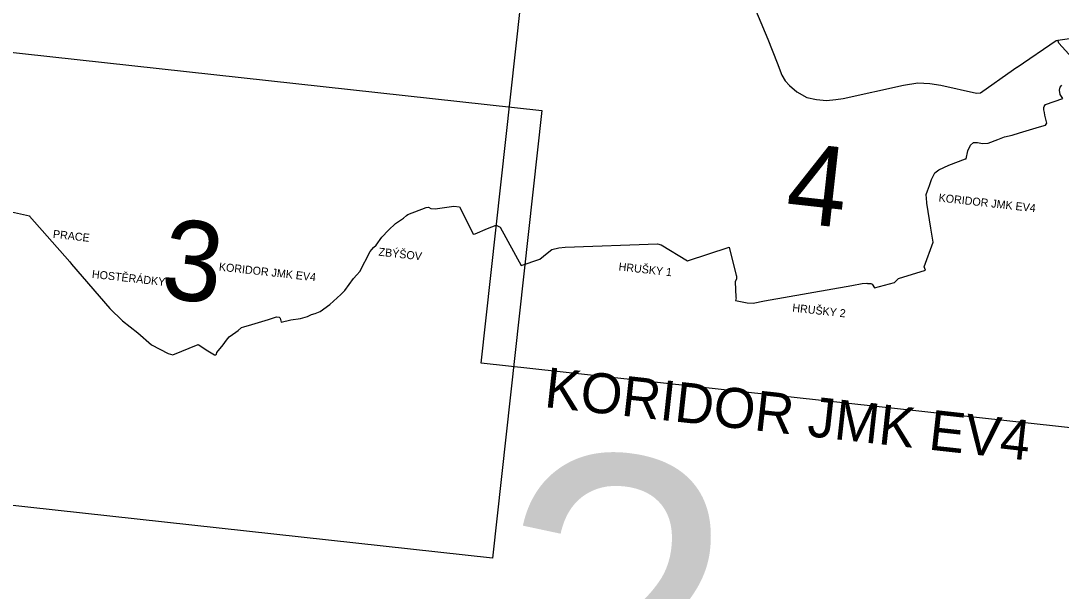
# Model space of a CAD drawing. Extents: x -678204 to -526855, y -1228851 to -1110393.
# Drawn here: x -587930 to -580130, y -1172295 to -1168017 of the extents above; entities that cross this region are included whole.
import ezdxf

# ---------------------------------------------------------------- set-up
doc = ezdxf.new("R2010")
doc.units = 0
for name, color, linetype in [('00_n_cyklo popisy', 7, 'Continuous'), ('00_n_cyklo popisy detaily', 7, 'Continuous'), ('00_n_cyklo provereni rekreacni hlavni', 7, 'Continuous'), ('00_n_cyklo provereni vedlejsi', 7, 'Continuous'), ('00_n_cyklo prujezdne podminecne rekreacni hlavni', 7, 'Continuous'), ('00_n_cyklo prujezdne rekreacni hlavni', 7, 'Continuous'), ('00_n_cyklo prujezdne rekreacni vedlejsi', 7, 'Continuous'), ('00_n_cyklo trasovani rekreacni hlavni', 7, 'Continuous'), ('00_n_cyklo trasovani rekreacni vedlejsi', 7, 'Continuous'), ('_HELP', 7, 'Continuous'), ('_HELP BIG', 7, 'Continuous')]:
    doc.layers.add(name, color=color, linetype=linetype)

msp = doc.modelspace()

# ---------------------------------------------------------------- linework, layer by layer
at = {"layer": '00_n_cyklo provereni rekreacni hlavni'}
for points in [[(-588022.2, -1169444.5), (-587865, -1169480.1), (-587863.6, -1169481.6)], [(-587863.6, -1169481.6), (-587562.9, -1169826)], [(-583983.3, -1169758.9), (-583948.4, -1169733.3), (-583896.6, -1169720.5), (-583848.6, -1169715.6), (-583156.9, -1169688.8), (-583128.3, -1169696.3), (-582931.7, -1169818.4)], [(-582565.7, -1169927.7), (-582565.3, -1169929.4), (-582563.9, -1169951.9), (-582573.4, -1169974.8), (-582568.6, -1170088.9), (-582567.1, -1170095.4), (-582572.3, -1170115.4)], [(-582572.3, -1170115.4), (-582483.1, -1170132.9), (-582440.1, -1170135), (-582353.7, -1170118.7), (-581698.9, -1170001.3), (-581623.3, -1169988.4), (-581588.2, -1169984.1), (-581582, -1169988.1), (-581567.5, -1169987.1), (-581555.9, -1169988.7), (-581546.4, -1169993.7)]]:
    msp.add_lwpolyline(points, dxfattribs=at)
at = {"layer": '00_n_cyklo provereni vedlejsi'}
msp.add_lwpolyline([(-582260.4, -1168332), (-582224.3, -1168425.4), (-582198.5, -1168468.4), (-582168.1, -1168503.5), (-582112.6, -1168551.1), (-582035.9, -1168591.4), (-581964.6, -1168608.6), (-581890.6, -1168614.5), (-581820.5, -1168608.6), (-581763.7, -1168599.3), (-581312.8, -1168499.8), (-581205.5, -1168483.6), (-581114.5, -1168487.6), (-581033.5, -1168499.8), (-580764.3, -1168560.5), (-580734, -1168558.5), (-580486.4, -1168382.1), (-580462.2, -1168364.7), (-580459, -1168364.7), (-580168.5, -1168166), (-580155.6, -1168161.8)], dxfattribs=at)
at = {"layer": '00_n_cyklo prujezdne podminecne rekreacni hlavni'}
for points in [[(-586258, -1170313.1), (-586196.7, -1170295), (-586072.9, -1170257.8), (-586012.1, -1170238.5), (-585993, -1170239.4), (-585986, -1170248.1), (-585978, -1170278.4), (-585904.1, -1170260.5), (-585831.8, -1170249), (-585781.4, -1170235.8), (-585749.4, -1170220.6), (-585722.1, -1170213.3), (-585684.9, -1170198), (-585612.1, -1170146), (-585530.3, -1170071), (-585500.4, -1170039.5), (-585435, -1169949.2), (-585409.7, -1169921.9), (-585388.9, -1169897.1), (-585311.5, -1169747.4), (-585286.7, -1169717.4), (-585266.8, -1169700.4), (-585223, -1169640.8), (-585174.1, -1169586.3), (-585121.3, -1169536.7), (-585060.6, -1169498.2), (-585039.1, -1169478), (-585029.1, -1169468.9), (-584891.3, -1169417.4), (-584874.1, -1169414.8), (-584856, -1169424.7), (-584823.5, -1169427.1), (-584683.7, -1169408.6), (-584640.2, -1169413.3)], [(-587562.9, -1169826), (-587548.7, -1169842.2), (-587262.5, -1170175.7)], [(-587262.5, -1170175.7), (-587167.7, -1170268.6), (-587051.1, -1170358.2), (-586950.3, -1170448.3), (-586825.3, -1170512.9), (-586790.9, -1170522.6), (-586599.5, -1170445.3), (-586526.7, -1170491.4)]]:
    msp.add_lwpolyline(points, dxfattribs=at)
at = {"layer": '00_n_cyklo prujezdne rekreacni hlavni'}
for points in [[(-579951, -1168402.3), (-580148, -1168184.7), (-580155.6, -1168161.8), (-579717.1, -1168101)], [(-581136.2, -1169385.7), (-581137.2, -1169379.4), (-581141.1, -1169321.2), (-581133.3, -1169292.9), (-581117.5, -1169253.5), (-581101.8, -1169207.1), (-581077.4, -1169156.8), (-581047.6, -1169134.8), (-580971.3, -1169100.2), (-580848.6, -1169052.2), (-580842.3, -1169052.2), (-580829.5, -1168991.7), (-580811.1, -1168949), (-580787.3, -1168928.8), (-580756.3, -1168931), (-580719.4, -1168936.9), (-580677.2, -1168936), (-580604.4, -1168906.8), (-580554.1, -1168887.4), (-580498.8, -1168875.3), (-580442, -1168857.4), (-580292.1, -1168813), (-580248, -1168798.9), (-580236.8, -1168784.6), (-580252.3, -1168726.1), (-580256.3, -1168703.7), (-580259.3, -1168684), (-580259.4, -1168667.2), (-580256.6, -1168658.8), (-580247.7, -1168644.6), (-580116.9, -1168600.6), (-580137.8, -1168569.4), (-580143.8, -1168536.6), (-580138.6, -1168514.2), (-580124.6, -1168499.2)], [(-581546.4, -1169993.7), (-581530.1, -1170020.4), (-581416.8, -1169989.9), (-581379.4, -1169979.6), (-581348.8, -1169950.6), (-581148.2, -1169888.4), (-581156.1, -1169863.2), (-581090, -1169677.5), (-581107.3, -1169573.7), (-581136.2, -1169385.7)], [(-584640.2, -1169413.3), (-584564.2, -1169564), (-584537.2, -1169616.7), (-584524.6, -1169615.6), (-584429.7, -1169574.1), (-584365, -1169549.8), (-584337, -1169564.8), (-584179.2, -1169852.7)], [(-584179.2, -1169852.7), (-584039.7, -1169804.9), (-583983.3, -1169758.9)], [(-582931.7, -1169818.4), (-582618.9, -1169714.9), (-582565.7, -1169927.7)], [(-586526.7, -1170491.4), (-586477.3, -1170522.7), (-586468.9, -1170522.4), (-586462.5, -1170517.3), (-586459.3, -1170505.3), (-586411.7, -1170448), (-586388.5, -1170413.1), (-586367.1, -1170388.3), (-586316.8, -1170353.2), (-586300.4, -1170339.5), (-586274.2, -1170317.8), (-586258, -1170313.1)]]:
    msp.add_lwpolyline(points, dxfattribs=at)
at = {"layer": '00_n_cyklo prujezdne rekreacni vedlejsi'}
msp.add_lwpolyline([(-582495.5, -1167760.7), (-582329, -1168154.9), (-582260.4, -1168332)], dxfattribs=at)
at = {"layer": '00_n_cyklo trasovani rekreacni hlavni'}
for points in [[(-579951, -1168402.3), (-580148, -1168184.7), (-580155.6, -1168161.8), (-579717.1, -1168101)], [(-581136.2, -1169385.7), (-581137.2, -1169379.4), (-581141.1, -1169321.2), (-581133.3, -1169292.9), (-581117.5, -1169253.5), (-581101.8, -1169207.1), (-581077.4, -1169156.8), (-581047.6, -1169134.8), (-580971.3, -1169100.2), (-580848.6, -1169052.2), (-580842.3, -1169052.2), (-580829.5, -1168991.7), (-580811.1, -1168949), (-580787.3, -1168928.8), (-580756.3, -1168931), (-580719.4, -1168936.9), (-580677.2, -1168936), (-580604.4, -1168906.8), (-580554.1, -1168887.4), (-580498.8, -1168875.3), (-580442, -1168857.4), (-580292.1, -1168813), (-580248, -1168798.9), (-580236.8, -1168784.6), (-580252.3, -1168726.1), (-580256.3, -1168703.7), (-580259.3, -1168684), (-580259.4, -1168667.2), (-580256.6, -1168658.8), (-580247.7, -1168644.6), (-580116.9, -1168600.6), (-580137.8, -1168569.4), (-580143.8, -1168536.6), (-580138.6, -1168514.2), (-580124.6, -1168499.2)], [(-581546.4, -1169993.7), (-581530.1, -1170020.4), (-581416.8, -1169989.9), (-581379.4, -1169979.6), (-581348.8, -1169950.6), (-581148.2, -1169888.4), (-581156.1, -1169863.2), (-581090, -1169677.5), (-581107.3, -1169573.7), (-581136.2, -1169385.7)], [(-588022.2, -1169444.5), (-587865, -1169480.1), (-587863.6, -1169481.6)], [(-586258, -1170313.1), (-586196.7, -1170295), (-586072.9, -1170257.8), (-586012.1, -1170238.5), (-585993, -1170239.4), (-585986, -1170248.1), (-585978, -1170278.4), (-585904.1, -1170260.5), (-585831.8, -1170249), (-585781.4, -1170235.8), (-585749.4, -1170220.6), (-585722.1, -1170213.3), (-585684.9, -1170198), (-585612.1, -1170146), (-585530.3, -1170071), (-585500.4, -1170039.5), (-585435, -1169949.2), (-585409.7, -1169921.9), (-585388.9, -1169897.1), (-585311.5, -1169747.4), (-585286.7, -1169717.4), (-585266.8, -1169700.4), (-585223, -1169640.8), (-585174.1, -1169586.3), (-585121.3, -1169536.7), (-585060.6, -1169498.2), (-585039.1, -1169478), (-585029.1, -1169468.9), (-584891.3, -1169417.4), (-584874.1, -1169414.8), (-584856, -1169424.7), (-584823.5, -1169427.1), (-584683.7, -1169408.6), (-584640.2, -1169413.3)], [(-584640.2, -1169413.3), (-584564.2, -1169564), (-584537.2, -1169616.7), (-584524.6, -1169615.6), (-584429.7, -1169574.1), (-584365, -1169549.8), (-584337, -1169564.8), (-584179.2, -1169852.7)], [(-587863.6, -1169481.6), (-587562.9, -1169826)], [(-583983.3, -1169758.9), (-583948.4, -1169733.3), (-583896.6, -1169720.5), (-583848.6, -1169715.6), (-583156.9, -1169688.8), (-583128.3, -1169696.3), (-582931.7, -1169818.4)], [(-584179.2, -1169852.7), (-584039.7, -1169804.9), (-583983.3, -1169758.9)], [(-582931.7, -1169818.4), (-582618.9, -1169714.9), (-582565.7, -1169927.7)], [(-587562.9, -1169826), (-587548.7, -1169842.2), (-587262.5, -1170175.7)], [(-582565.7, -1169927.7), (-582565.3, -1169929.4), (-582563.9, -1169951.9), (-582573.4, -1169974.8), (-582568.6, -1170088.9), (-582567.1, -1170095.4), (-582572.3, -1170115.4)], [(-582572.3, -1170115.4), (-582483.1, -1170132.9), (-582440.1, -1170135), (-582353.7, -1170118.7), (-581698.9, -1170001.3), (-581623.3, -1169988.4), (-581588.2, -1169984.1), (-581582, -1169988.1), (-581567.5, -1169987.1), (-581555.9, -1169988.7), (-581546.4, -1169993.7)], [(-587262.5, -1170175.7), (-587167.7, -1170268.6), (-587051.1, -1170358.2), (-586950.3, -1170448.3), (-586825.3, -1170512.9), (-586790.9, -1170522.6), (-586599.5, -1170445.3), (-586526.7, -1170491.4)], [(-586526.7, -1170491.4), (-586477.3, -1170522.7), (-586468.9, -1170522.4), (-586462.5, -1170517.3), (-586459.3, -1170505.3), (-586411.7, -1170448), (-586388.5, -1170413.1), (-586367.1, -1170388.3), (-586316.8, -1170353.2), (-586300.4, -1170339.5), (-586274.2, -1170317.8), (-586258, -1170313.1)]]:
    msp.add_lwpolyline(points, dxfattribs=at)
at = {"layer": '00_n_cyklo trasovani rekreacni vedlejsi'}
for points in [[(-582495.5, -1167760.7), (-582329, -1168154.9), (-582260.4, -1168332)], [(-582260.4, -1168332), (-582224.3, -1168425.4), (-582198.5, -1168468.4), (-582168.1, -1168503.5), (-582112.6, -1168551.1), (-582035.9, -1168591.4), (-581964.6, -1168608.6), (-581890.6, -1168614.5), (-581820.5, -1168608.6), (-581763.7, -1168599.3), (-581312.8, -1168499.8), (-581205.5, -1168483.6), (-581114.5, -1168487.6), (-581033.5, -1168499.8), (-580764.3, -1168560.5), (-580734, -1168558.5), (-580486.4, -1168382.1), (-580462.2, -1168364.7), (-580459, -1168364.7), (-580168.5, -1168166), (-580155.6, -1168161.8)]]:
    msp.add_lwpolyline(points, dxfattribs=at)
at = {"layer": '_HELP'}
for points in [[(-584109.1, -1167226.8), (-579394.6, -1167744.5), (-579763.3, -1171102), (-584477.8, -1170584.3)], [(-588739.2, -1168172.5), (-584024.6, -1168690.2), (-584393.3, -1172047.7), (-589107.9, -1171530)]]:
    msp.add_lwpolyline(points, close=True, dxfattribs=at)

# ---------------------------------------------------------------- texts
at = {"layer": '00_n_cyklo popisy'}
msp.add_text('KORIDOR JMK EV4', height=300, rotation=353.68355, dxfattribs=at).set_placement((-584011.8, -1170913.4))
at = {"layer": '00_n_cyklo popisy detaily'}
for s, p in [('KORIDOR JMK EV4', (-581051.2, -1169372.1)), ('PRACE', (-587691.3, -1169644.8)), ('ZBÝŠOV', (-585250, -1169778.2)), ('KORIDOR JMK EV4', (-586447, -1169890.1)), ('HRUŠKY 1', (-583450.3, -1169889.4)), ('HOSTĚRÁDKY', (-587399.1, -1169945.2)), ('HRUŠKY 2', (-582148, -1170197.9))]:
    msp.add_text(s, height=60, rotation=353.68355, dxfattribs=at).set_placement(p)
at = {"layer": '_HELP'}
for s, p in [('4', (-582209, -1169521.9)), ('3', (-586892.9, -1170092))]:
    msp.add_text(s, height=600, rotation=353.68355, dxfattribs=at).set_placement(p)
at = {"layer": '_HELP BIG'}
msp.add_text('2', height=2400, rotation=353.68355, dxfattribs=at).set_placement((-584537.8, -1173580.8))

doc.saveas('drawing.dxf')
